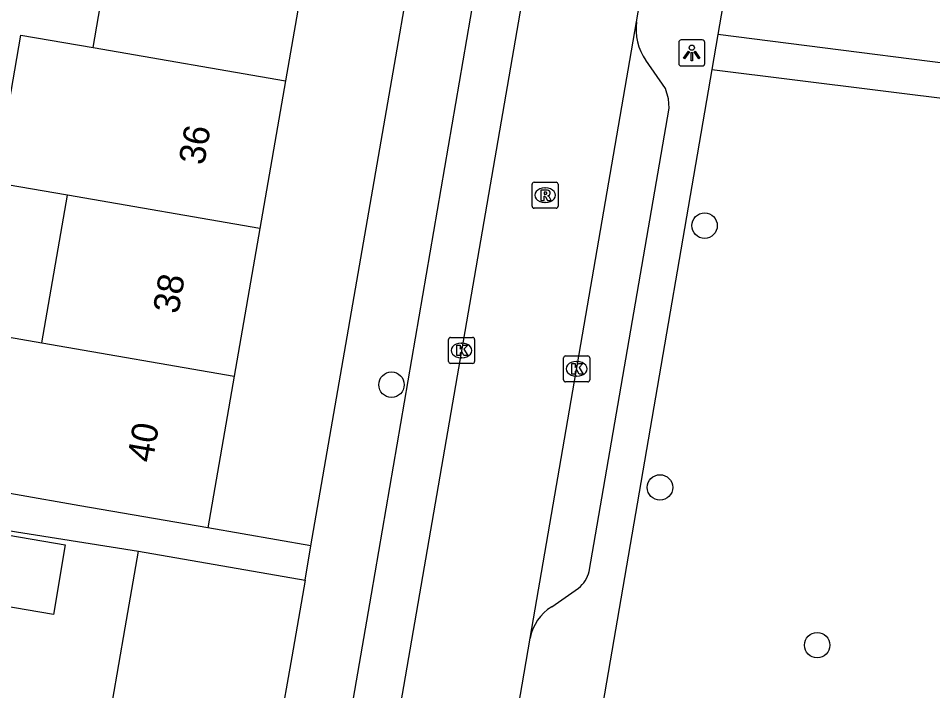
# Model space of a CAD drawing. Extents: x 159822 to 160765, y 380693 to 381634.
# Drawn here: x 160157.76 to 160192.9, y 380894.34 to 380920.19 of the extents above; entities that cross this region are included whole.
import ezdxf

# ---------------------------------------------------------------- set-up
doc = ezdxf.new("R2010")
doc.units = 0
for name, color, linetype in [('IMGEO_Boom', 7, 'Continuous'), ('IMGEO_Kolk', 7, 'Continuous'), ('IMGEO_Lichtpunt', 7, 'Continuous'), ('IMGEO_Pand', 7, 'Continuous'), ('IMGEO_Pand_nummerreeks', 7, 'Continuous'), ('IMGEO_Rijbaan_lokaal_open', 7, 'Continuous'), ('IMGEO_Rioolput', 7, 'Continuous'), ('IMGEO_Voetpad_halfverhard', 7, 'Continuous'), ('IMGEO_Voetpad_open', 7, 'Continuous')]:
    doc.layers.add(name, color=color, linetype=linetype)

msp = doc.modelspace()

# ---------------------------------------------------------------- linework, layer by layer
at = {"layer": 'IMGEO_Boom'}
for centre in [(160184.138, 380912.22), (160172.108, 380906.104), (160182.424, 380902.156), (160188.465, 380896.089)]:
    msp.add_circle(centre, 0.489, dxfattribs=at)
at = {"layer": 'IMGEO_Kolk'}
for p, q in [((160174.298, 380906.996), (160174.298, 380907.848)), ((160174.373, 380907.922), (160175.225, 380907.922)), ((160174.786, 380907.702), (160174.811, 380907.702)), ((160175.299, 380907.848), (160175.299, 380906.996)), ((160175.225, 380906.922), (160174.373, 380906.922)), ((160174.809, 380907.142), (160174.784, 380907.142)), ((160178.721, 380906.288), (160178.721, 380907.14)), ((160178.796, 380907.214), (160179.648, 380907.214)), ((160179.209, 380906.994), (160179.234, 380906.994)), ((160179.722, 380907.14), (160179.722, 380906.288)), ((160179.648, 380906.214), (160178.796, 380906.214)), ((160179.232, 380906.434), (160179.207, 380906.434))]:
    msp.add_line(p, q, dxfattribs=at)
for points in [[(160174.298, 380906.996), (160174.298, 380907.848)], [(160174.373, 380907.922), (160175.225, 380907.922)], [(160174.619, 380907.622), (160174.742, 380907.622), (160174.742, 380907.471), (160174.872, 380907.622), (160175.036, 380907.622), (160174.89, 380907.471), (160175.043, 380907.222), (160174.891, 380907.222), (160174.806, 380907.386), (160174.742, 380907.319), (160174.742, 380907.222), (160174.619, 380907.222), (160174.619, 380907.622)], [(160175.299, 380907.848), (160175.299, 380906.996)], [(160175.225, 380906.922), (160174.373, 380906.922)], [(160178.721, 380906.288), (160178.721, 380907.14)], [(160178.796, 380907.214), (160179.648, 380907.214)], [(160179.042, 380906.914), (160179.165, 380906.914), (160179.165, 380906.763), (160179.295, 380906.914), (160179.459, 380906.914), (160179.313, 380906.763), (160179.466, 380906.514), (160179.314, 380906.514), (160179.229, 380906.678), (160179.165, 380906.611), (160179.165, 380906.514), (160179.042, 380906.514), (160179.042, 380906.914)], [(160179.722, 380907.14), (160179.722, 380906.288)], [(160179.648, 380906.214), (160178.796, 380906.214)]]:
    msp.add_lwpolyline(points, dxfattribs=at)
for centre, start, end in [((160174.375, 380907.846), 91.552, 178.448), ((160174.375, 380907.846), 91.552, 178.448), ((160175.223, 380907.846), 1.552, 88.448), ((160175.223, 380907.846), 1.552, 88.448), ((160174.375, 380906.998), 181.552, 268.448), ((160174.375, 380906.998), 181.552, 268.448), ((160175.223, 380906.998), 271.552, 358.448), ((160175.223, 380906.998), 271.552, 358.448), ((160178.798, 380907.138), 91.552, 178.448), ((160178.798, 380907.138), 91.552, 178.448), ((160179.646, 380907.138), 1.552, 88.448), ((160179.646, 380907.138), 1.552, 88.448), ((160178.798, 380906.29), 181.552, 268.448), ((160178.798, 380906.29), 181.552, 268.448), ((160179.646, 380906.29), 271.552, 358.448), ((160179.646, 380906.29), 271.552, 358.448)]:
    msp.add_arc(centre, 0.0765, start, end, dxfattribs=at)
for centre, major_axis, ratio, start_param, end_param in [((160174.785, 380907.422), (-0.387, 0.002), 0.722429, 4.712389, 7.853982), ((160174.81, 380907.422), (-0.39, 0.002), 0.717154, 1.570796, 4.712389), ((160179.208, 380906.714), (-0.387, 0.002), 0.722429, 4.712389, 7.853982), ((160179.233, 380906.714), (-0.39, 0.002), 0.717154, 1.570796, 4.712389)]:
    msp.add_ellipse(centre, major_axis=major_axis, ratio=ratio, start_param=start_param, end_param=end_param, dxfattribs=at)
at = {"layer": 'IMGEO_Lichtpunt'}
for p, q in [((160183.147, 380919.264), (160183.147, 380918.457)), ((160183.147, 380919.264), (160183.147, 380918.457)), ((160184.049, 380919.359), (160183.241, 380919.359)), ((160184.049, 380919.359), (160183.241, 380919.359)), ((160184.143, 380918.457), (160184.143, 380919.264)), ((160184.143, 380918.457), (160184.143, 380919.264)), ((160183.241, 380918.363), (160184.049, 380918.363)), ((160183.241, 380918.363), (160184.049, 380918.363))]:
    msp.add_line(p, q, dxfattribs=at)
for points in [[(160183.521, 380918.928), (160183.56, 380918.9), (160183.372, 380918.638), (160183.334, 380918.665), (160183.521, 380918.928)], [(160183.623, 380918.88), (160183.67, 380918.88), (160183.67, 380918.558), (160183.623, 380918.558), (160183.623, 380918.88)], [(160183.733, 380918.9), (160183.771, 380918.927), (160183.958, 380918.665), (160183.919, 380918.637), (160183.733, 380918.9)]]:
    msp.add_lwpolyline(points, dxfattribs=at)
msp.add_circle((160183.646, 380919.062), 0.0994, dxfattribs=at)
for centre, start, end in [((160183.241, 380919.264), 90, 180), ((160183.241, 380919.264), 90, 180), ((160184.049, 380919.264), 0, 90), ((160184.049, 380919.264), 0, 90), ((160183.241, 380918.457), 180, 270), ((160183.241, 380918.457), 180, 270), ((160184.049, 380918.457), 270, 0), ((160184.049, 380918.457), 270, 360)]:
    msp.add_arc(centre, 0.0946, start, end, dxfattribs=at)
at = {"layer": 'IMGEO_Pand'}
for points in [[(160160.636, 380919.066), (160161.621, 380924.741)], [(160169.015, 380923.457), (160168.031, 380917.782)], [(160159.652, 380913.391), (160156.878, 380913.872), (160157.862, 380919.547), (160160.636, 380919.066)], [(160160.636, 380919.066), (160168.031, 380917.782)], [(160168.031, 380917.782), (160167.047, 380912.107)], [(160158.668, 380907.718), (160159.652, 380913.391)], [(160167.047, 380912.107), (160159.652, 380913.391)], [(160167.047, 380912.107), (160166.063, 380906.434)], [(160154.418, 380902.441), (160155.43, 380908.28), (160158.668, 380907.718)], [(160158.668, 380907.718), (160166.063, 380906.434)], [(160166.063, 380906.434), (160165.051, 380900.598)], [(160165.051, 380900.598), (160160.125, 380901.452), (160157.656, 380901.88), (160154.418, 380902.441)], [(160156.041, 380900.544), (160159.564, 380899.949), (160159.112, 380897.272), (160155.589, 380897.867), (160156.041, 380900.544)], [(160167.783, 380892.824), (160161.379, 380893.935), (160161.868, 380896.754), (160162.379, 380899.699)], [(160162.379, 380899.699), (160168.783, 380898.588)], [(160168.783, 380898.588), (160168.272, 380895.643), (160167.783, 380892.824)]]:
    msp.add_lwpolyline(points, dxfattribs=at)
at = {"layer": 'IMGEO_Rijbaan_lokaal_open'}
for points in [[(160181.868, 380948.362), (160170.586, 380883.008)], [(160181.524, 380920.061), (160181.862, 380922.086)], [(160177.432, 380896.355), (160181.524, 380920.061)], [(160173.482, 380873.675), (160173.748, 380874.839), (160177.432, 380896.355)]]:
    msp.add_lwpolyline(points, dxfattribs=at)
at = {"layer": 'IMGEO_Rioolput'}
for p, q in [((160177.509, 380912.964), (160177.509, 380913.816)), ((160177.584, 380913.89), (160178.436, 380913.89)), ((160177.997, 380913.67), (160178.022, 380913.67)), ((160178.51, 380913.816), (160178.51, 380912.964)), ((160178.436, 380912.89), (160177.584, 380912.89)), ((160178.02, 380913.11), (160177.995, 380913.11))]:
    msp.add_line(p, q, dxfattribs=at)
for points in [[(160177.509, 380912.964), (160177.509, 380913.816)], [(160177.584, 380913.89), (160178.436, 380913.89)], [(160178.098, 380913.588), (160177.846, 380913.59), (160177.846, 380913.19)], [(160178.51, 380913.816), (160178.51, 380912.964)], [(160177.846, 380913.19), (160177.97, 380913.19), (160177.97, 380913.352), (160177.981, 380913.352)], [(160178.024, 380913.509), (160177.97, 380913.509), (160177.97, 380913.428)], [(160177.97, 380913.428), (160178.022, 380913.428)], [(160178.028, 380913.323), (160178.099, 380913.19), (160178.239, 380913.19), (160178.174, 380913.316)], [(160178.436, 380912.89), (160177.584, 380912.89)]]:
    msp.add_lwpolyline(points, dxfattribs=at)
for centre, radius, start, end in [((160177.586, 380913.814), 0.0765, 91.552, 178.448), ((160177.586, 380913.814), 0.0765, 91.552, 178.448), ((160178.097, 380913.478), 0.109, 350.3612, 89.416), ((160178.434, 380913.814), 0.0765, 1.552, 88.448), ((160178.434, 380913.814), 0.0765, 1.552, 88.448), ((160177.98, 380913.299), 0.0533, 26.0293, 88.6989), ((160178.006, 380913.617), 0.19, 274.7715, 282.9687), ((160178.03, 380913.413), 0.0964, 77.0061, 93.1865), ((160178.044, 380913.47), 0.0378, 276.6634, 79.6772), ((160178.095, 380913.478), 0.112, 277.5842, 350.9817), ((160178.079, 380913.263), 0.108, 29.5134, 73.7905), ((160177.586, 380912.966), 0.0765, 181.552, 268.448), ((160177.586, 380912.966), 0.0765, 181.552, 268.448), ((160178.434, 380912.966), 0.0765, 271.552, 358.448), ((160178.434, 380912.966), 0.0765, 271.552, 358.448)]:
    msp.add_arc(centre, radius, start, end, dxfattribs=at)
for centre, major_axis, ratio, start_param, end_param in [((160177.996, 380913.39), (-0.387, 0.002), 0.722429, 4.712389, 7.853982), ((160178.021, 380913.39), (-0.39, 0.002), 0.717154, 1.570796, 4.712389)]:
    msp.add_ellipse(centre, major_axis=major_axis, ratio=ratio, start_param=start_param, end_param=end_param, dxfattribs=at)
at = {"layer": 'IMGEO_Voetpad_halfverhard'}
for points in [[(160197.526, 380917.93), (160184.645, 380919.573)], [(160184.414, 380918.229), (160197.276, 380916.618)]]:
    msp.add_lwpolyline(points, dxfattribs=at)
at = {"layer": 'IMGEO_Voetpad_open'}
for points in [[(160189.482, 380947.418), (160188.75, 380943.396), (160184.645, 380919.573)], [(160169.341, 380886.418), (160170.703, 380894.348), (160171.339, 380898.056), (160179.65, 380946.461)], [(160169.012, 380899.911), (160175.956, 380939.958)], [(160184.645, 380919.573), (160184.414, 380918.229)], [(160179.701, 380898.922), (160182.771, 380916.731), (160182.75, 380917.094), (160182.636, 380917.497), (160181.886, 380918.576)], [(160184.414, 380918.229), (160178.549, 380884.079)], [(160153.97, 380901.04), (160162.379, 380899.699)], [(160169.012, 380899.911), (160165.051, 380900.598)], [(160168.783, 380898.588), (160169.012, 380899.911)], [(160178.264, 380897.567), (160179.292, 380898.285)]]:
    msp.add_lwpolyline(points, dxfattribs=at)
for centre, radius, start, end in [((160183.559, 380919.77), 2.056, 171.8754, 215.5243), ((160178.555, 380899.208), 1.181, 308.6095, 345.9837), ((160179.231, 380896.011), 1.832, 121.8745, 169.1887)]:
    msp.add_arc(centre, radius, start, end, dxfattribs=at)

# ---------------------------------------------------------------- texts
at = {"layer": 'IMGEO_Pand_nummerreeks'}
for s, p in [('36', (160164.907, 380914.517)), ('38', (160163.916, 380908.799)), ('40', (160162.924, 380903.078))]:
    msp.add_text(s, height=1, rotation=80.1615, dxfattribs=at).set_placement(p)

doc.saveas('drawing.dxf')
